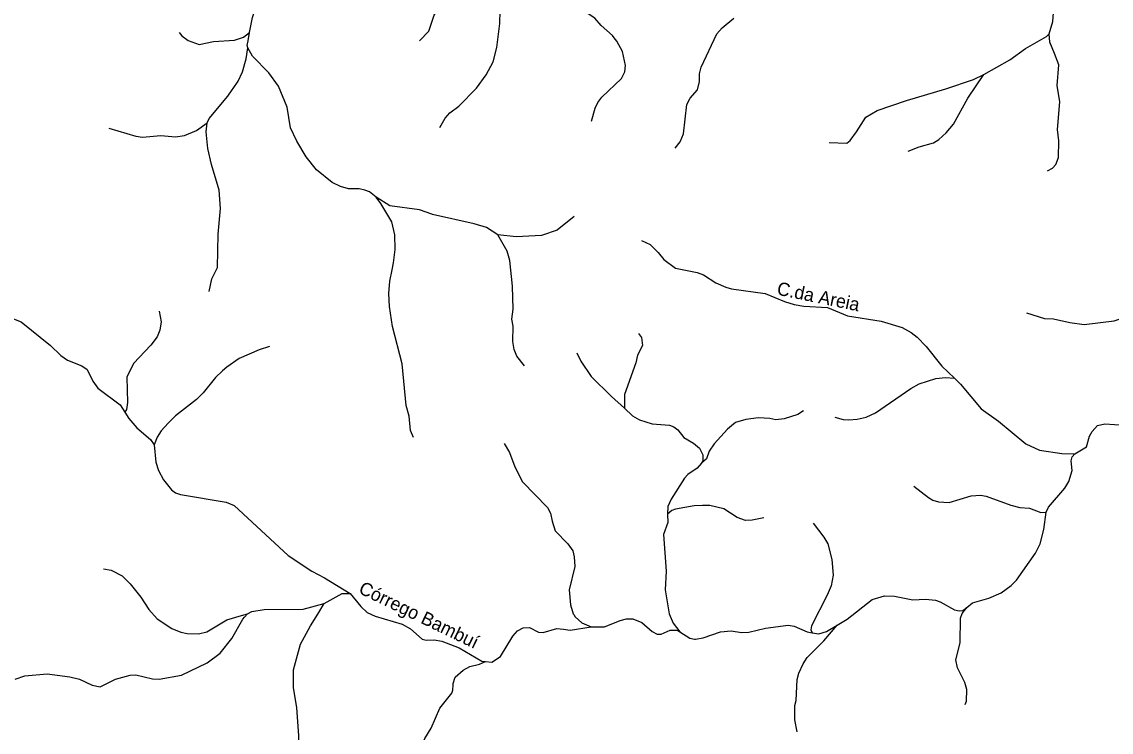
# Model space of a CAD drawing. Extents: x 473.9 to 500, y 7733.1 to 7760.8.
# Drawn here: x 487.72 to 494.3, y 7748.41 to 7752.7 of the extents above; entities that cross this region are included whole.
import ezdxf
from ezdxf.enums import TextEntityAlignment as Align

# ---------------------------------------------------------------- set-up
doc = ezdxf.new("R2010")
doc.units = 0
doc.header["$LTSCALE"] = 0.032
doc.layers.add('61', color=7, linetype='Continuous')
doc.layers.add('7', color=7, linetype='Continuous', lineweight=25)

msp = doc.modelspace()

# ---------------------------------------------------------------- linework, layer by layer
at = {"layer": '7'}
for points in [[(489.0978, 7752.6322), (489.1167, 7752.7232), (489.1826, 7752.9159), (489.2833, 7753.1268), (489.309, 7753.204), (489.3106, 7753.3927), (489.3298, 7753.4744), (489.3874, 7753.6027), (489.4117, 7753.6834), (489.4117, 7753.7508), (489.3957, 7753.837)], [(493.9278, 7752.6245), (493.9488, 7752.6981), (493.9547, 7752.7762), (493.9572, 7752.8085), (493.989, 7752.8897), (493.9899, 7752.984), (494, 7753.0158), (494.0416, 7753.0831), (494.0717, 7753.1527), (494.1019, 7753.199), (494.158, 7753.2503), (494.2408, 7753.2987)], [(490.1257, 7752.5825), (490.1808, 7752.6398), (490.2143, 7752.7373), (490.2748, 7752.8186), (490.3281, 7752.873), (490.4074, 7752.937), (490.4215, 7752.9588), (490.4461, 7753.0279), (490.4572, 7753.0844), (490.4612, 7753.1473)], [(490.2469, 7752.0579), (490.2808, 7752.1147), (490.3075, 7752.1466), (490.3632, 7752.1879), (490.4689, 7752.2953), (490.5273, 7752.3771), (490.5709, 7752.4549), (490.592, 7752.5405), (490.6095, 7752.6857), (490.6112, 7752.7625), (490.6078, 7752.8904), (490.5948, 7752.9581), (490.5682, 7753.0238), (490.5298, 7753.0816), (490.4612, 7753.1473)], [(491.1644, 7752.0963), (491.1858, 7752.1755), (491.2012, 7752.2098), (491.2269, 7752.2418), (491.3449, 7752.3536), (491.3649, 7752.3945), (491.368, 7752.4324), (491.3508, 7752.5182), (491.3173, 7752.5789), (491.3014, 7752.599), (491.29, 7752.6134), (491.222, 7752.6734), (491.1831, 7752.7195), (491.1264, 7752.757), (491.1058, 7752.7784), (491.084, 7752.8101), (491.0682, 7752.8725), (491.0895, 7752.934), (491.1537, 7753.0282), (491.1957, 7753.075), (491.2909, 7753.1607)], [(491.6683, 7751.9332), (491.6991, 7751.9725), (491.72, 7752.0205), (491.7402, 7752.1976), (491.7597, 7752.2349), (491.8034, 7752.2851), (491.8154, 7752.3364), (491.8155, 7752.382), (491.8249, 7752.4228), (491.9214, 7752.6246), (491.953, 7752.6609), (492.0237, 7752.718)], [(488.6739, 7752.6329), (488.6908, 7752.6119), (488.7275, 7752.5847), (488.7937, 7752.5602), (488.8816, 7752.5779), (489.0076, 7752.5854), (489.0631, 7752.6047), (489.0978, 7752.6322)], [(489.0885, 7752.5396), (489.0853, 7752.5526), (489.0898, 7752.5815), (489.0978, 7752.6322)], [(493.533, 7752.3781), (493.6895, 7752.4673), (493.7849, 7752.5363), (493.9107, 7752.6086), (493.9278, 7752.6245)], [(493.9169, 7751.7957), (493.9473, 7751.8136), (493.9673, 7751.8344), (493.9834, 7751.8762), (493.985, 7751.9779), (493.9779, 7752.0458), (493.9906, 7752.2137), (493.9747, 7752.3113), (493.985, 7752.4375), (493.9585, 7752.5056), (493.9321, 7752.5734), (493.9278, 7752.6245)], [(488.8427, 7752.0858), (488.8552, 7752.1123), (488.9685, 7752.2469), (488.9948, 7752.2864), (489, 7752.2942), (489.0294, 7752.3383), (489.0556, 7752.3939), (489.0782, 7752.4731), (489.0885, 7752.5396)], [(489.8633, 7751.6369), (489.8237, 7751.6692), (489.7941, 7751.6796), (489.7612, 7751.687), (489.6968, 7751.6879), (489.6477, 7751.7012), (489.5976, 7751.7263), (489.5038, 7751.8034), (489.4405, 7751.881), (489.3848, 7751.9765), (489.3461, 7752.0571), (489.3265, 7752.1817), (489.2747, 7752.3089), (489.215, 7752.3888), (489.1164, 7752.4898), (489.0885, 7752.5396)], [(492.5981, 7751.9672), (492.706, 7751.9629), (492.7252, 7751.9794), (492.7643, 7752.0312), (492.8193, 7752.1205), (492.8893, 7752.1612), (493.0666, 7752.2219), (493.3026, 7752.291), (493.471, 7752.3488), (493.533, 7752.3781)], [(493.0755, 7751.915), (493.1426, 7751.9426), (493.2294, 7751.9667), (493.2604, 7751.9852), (493.3049, 7752.0259), (493.3502, 7752.0778), (493.436, 7752.2365), (493.533, 7752.3781)], [(488.2502, 7752.0542), (488.4126, 7752.0054), (488.4517, 7752.0006), (488.563, 7752.0102), (488.651, 7752.0014), (488.7058, 7752.0109), (488.7781, 7752.0405), (488.8427, 7752.0858)], [(488.8554, 7751.0685), (488.8719, 7751.1444), (488.905, 7751.213), (488.9098, 7751.4151), (488.9227, 7751.5689), (488.9162, 7751.679), (488.8697, 7751.8342), (488.8473, 7751.9323), (488.8377, 7752.0327), (488.8427, 7752.0858)], [(490.0895, 7750.1852), (490.0708, 7750.2291), (490.0627, 7750.316), (490.0443, 7750.3804), (490.0201, 7750.631), (489.9611, 7750.8574), (489.9441, 7750.9779), (489.9409, 7751.0559), (489.9457, 7751.1297), (489.9598, 7751.1996), (489.9682, 7751.2416), (489.9778, 7751.3225), (489.9761, 7751.4102), (489.9576, 7751.4885), (489.8916, 7751.5999), (489.8633, 7751.6369)], [(490.5985, 7751.4106), (490.5305, 7751.4553), (490.455, 7751.4771), (490.2041, 7751.5329), (490.1994, 7751.5346), (490.1241, 7751.5614), (489.9463, 7751.5858), (489.8633, 7751.6369)], [(491.0581, 7751.5206), (490.9562, 7751.4386), (490.8613, 7751.4068), (490.709, 7751.3975), (490.5985, 7751.4106)], [(490.7592, 7750.6195), (490.712, 7750.6771), (490.6961, 7750.7171), (490.6882, 7750.7656), (490.6906, 7750.8578), (490.6834, 7750.9002), (490.6898, 7750.9618), (490.6873, 7751.1008), (490.6696, 7751.2556), (490.6535, 7751.3121), (490.5985, 7751.4106)], [(491.4659, 7751.3769), (491.5174, 7751.3516), (491.5666, 7751.3032), (491.6, 7751.2603), (491.6717, 7751.2097), (491.8017, 7751.1833), (491.8395, 7751.1682), (491.9154, 7751.1198), (491.9748, 7751.0941), (492.0098, 7751.0841), (492.2128, 7751.0561), (492.3292, 7751.0077), (492.3874, 7750.99), (492.4451, 7750.9797), (492.5886, 7750.971), (492.7104, 7750.9201), (492.9125, 7750.8892), (493.0389, 7750.85), (493.094, 7750.8213), (493.1309, 7750.7924), (493.1854, 7750.7348), (493.2795, 7750.6173), (493.355, 7750.5446)], [(487.5104, 7750.9522), (487.5248, 7750.9443), (487.5467, 7750.9322), (487.6635, 7750.9078), (487.7193, 7750.8848), (487.8966, 7750.7414), (487.9591, 7750.6809), (487.9995, 7750.6532), (488.0858, 7750.6197), (488.1184, 7750.5966), (488.1518, 7750.5266), (488.1819, 7750.4843), (488.3172, 7750.3825), (488.3468, 7750.3398)], [(488.5529, 7750.9487), (488.5658, 7750.884), (488.5571, 7750.8342), (488.541, 7750.7939), (488.503, 7750.7431), (488.3976, 7750.634), (488.3583, 7750.5509), (488.3613, 7750.3971), (488.3557, 7750.3545), (488.3468, 7750.3398)], [(493.7905, 7750.939), (493.8997, 7750.9054), (493.954, 7750.9029), (494.0511, 7750.8812), (494.138, 7750.8693), (494.3198, 7750.8913), (494.4091, 7750.9209), (494.4388, 7750.9308), (494.5097, 7750.9269), (494.635, 7750.8941), (494.6673, 7750.8998)], [(491.4469, 7750.814), (491.466, 7750.7899), (491.4706, 7750.7425), (491.4416, 7750.6842), (491.4319, 7750.6377), (491.3632, 7750.4455), (491.3622, 7750.3635)], [(489.2184, 7750.7352), (489.157, 7750.7153), (489.037, 7750.6642), (488.9618, 7750.6117), (488.9363, 7750.5883), (488.8939, 7750.5495), (488.8185, 7750.4563), (488.778, 7750.4152), (488.6511, 7750.3179), (488.6065, 7750.2733), (488.5655, 7750.2266), (488.5408, 7750.1874), (488.5232, 7750.1416)], [(491.0761, 7750.6982), (491.0999, 7750.6469), (491.1626, 7750.5547), (491.2836, 7750.4332), (491.3622, 7750.3635)], [(492.6325, 7750.3096), (492.6823, 7750.2958), (492.718, 7750.2927), (492.7668, 7750.2965), (492.8215, 7750.3093), (492.878, 7750.335), (493.0909, 7750.4813), (493.1431, 7750.5108), (493.2423, 7750.5428), (493.3014, 7750.5486), (493.355, 7750.5446)], [(493.355, 7750.5446), (493.3925, 7750.5085), (493.517, 7750.3599), (493.6216, 7750.2857), (493.7869, 7750.1472), (493.8678, 7750.1096), (494.0027, 7750.0893), (494.0813, 7750.088)], [(488.3468, 7750.3398), (488.3696, 7750.3012), (488.4185, 7750.2436), (488.5005, 7750.1751), (488.5232, 7750.1416)], [(491.3622, 7750.3635), (491.412, 7750.3164), (491.4534, 7750.2932), (491.5309, 7750.268), (491.6342, 7750.2598), (491.6599, 7750.251), (491.6841, 7750.2332), (491.7202, 7750.1853), (491.7795, 7750.1528), (491.8165, 7750.1217), (491.8361, 7750.0821), (491.8355, 7750.0466), (491.8273, 7750.0305)], [(492.4435, 7750.3478), (492.4101, 7750.3252), (492.3272, 7750.2984), (492.2773, 7750.2935), (492.24, 7750.3016), (492.1724, 7750.3047), (492.0961, 7750.2951), (492.0333, 7750.2766), (491.9852, 7750.2372), (491.905, 7750.1474), (491.8749, 7750.103), (491.8586, 7750.0571), (491.8273, 7750.0305)], [(494.0813, 7750.088), (494.1534, 7750.1295), (494.1716, 7750.1938), (494.1859, 7750.2224), (494.219, 7750.2588), (494.2637, 7750.2686), (494.38, 7750.2599), (494.4179, 7750.2662)], [(488.5232, 7750.1416), (488.5323, 7750.0378), (488.5495, 7749.9879), (488.5798, 7749.9302), (488.6279, 7749.8705), (488.6526, 7749.8522), (488.6826, 7749.8415), (488.9569, 7749.7947), (489.007, 7749.7759), (489.332, 7749.4742), (489.4747, 7749.3794), (489.5522, 7749.339), (489.7059, 7749.245)], [(490.6355, 7750.1505), (490.6687, 7750.0966), (490.7011, 7750.0095), (490.7468, 7749.9181), (490.8984, 7749.7633), (490.9167, 7749.7287), (490.9255, 7749.6806), (490.9449, 7749.6227), (491.021, 7749.5444), (491.0504, 7749.5021), (491.0594, 7749.4654), (491.0625, 7749.408), (491.0297, 7749.2659), (491.0361, 7749.1761), (491.0539, 7749.1211), (491.0571, 7749.1165), (491.0655, 7749.104), (491.1056, 7749.0678), (491.1612, 7749.043)], [(493.9084, 7749.7359), (493.9227, 7749.765), (494.0223, 7749.8809), (494.0467, 7749.9196), (494.0652, 7749.9876), (494.0596, 7750.0445), (494.0657, 7750.0687), (494.0813, 7750.088)], [(491.8273, 7750.0305), (491.8007, 7750.0013), (491.7454, 7749.9629), (491.7251, 7749.941), (491.6443, 7749.8134), (491.6249, 7749.7698), (491.6235, 7749.7229)], [(493.1107, 7749.8921), (493.1983, 7749.8233), (493.2241, 7749.8075), (493.2586, 7749.7985), (493.3233, 7749.7941), (493.4555, 7749.8349), (493.5133, 7749.8382), (493.5462, 7749.8323), (493.6955, 7749.7773), (493.7506, 7749.7636), (493.8093, 7749.7586), (493.8776, 7749.7336), (493.9084, 7749.7359)], [(492.2033, 7749.7008), (492.1332, 7749.6866), (492.0941, 7749.6858), (492.0426, 7749.7036), (491.9624, 7749.7562), (491.8774, 7749.7756), (491.8329, 7749.7748), (491.7836, 7749.774), (491.6714, 7749.7532), (491.6485, 7749.7457), (491.6235, 7749.7229)], [(493.4302, 7749.1605), (493.4647, 7749.188), (493.5625, 7749.2154), (493.6377, 7749.2485), (493.6978, 7749.2927), (493.7306, 7749.3256), (493.8449, 7749.4872), (493.8728, 7749.5446), (493.8952, 7749.6309), (493.9084, 7749.7359)], [(491.6235, 7749.7229), (491.6246, 7749.6733), (491.5974, 7749.6008), (491.6141, 7749.3795), (491.6086, 7749.2665), (491.6335, 7749.121), (491.6576, 7749.0657), (491.6963, 7749.0127)], [(492.5023, 7749.6697), (492.5669, 7749.5845), (492.5903, 7749.5436), (492.6156, 7749.4487), (492.6237, 7749.3546), (492.6112, 7749.2908), (492.5874, 7749.2332), (492.4917, 7749.0486), (492.4882, 7749.0251), (492.4954, 7749.0059)], [(488.2179, 7749.3934), (488.2639, 7749.384), (488.3301, 7749.35), (488.3788, 7749.3028), (488.4425, 7749.2221), (488.491, 7749.1468), (488.5407, 7749.091), (488.6305, 7749.032), (488.6834, 7749.0103), (488.7215, 7749.0027), (488.7913, 7749.0011), (488.8417, 7749.0116), (488.9619, 7749.0844), (489.05, 7749.1107), (489.0857, 7749.1213)], [(489.5501, 7749.1833), (489.6585, 7749.2431), (489.7059, 7749.245)], [(489.7059, 7749.245), (489.7705, 7749.1662), (489.8092, 7749.1297), (489.8578, 7749.1068), (490.0197, 7749.0595), (490.0701, 7749.0304), (490.1416, 7748.9689), (490.1657, 7748.9619), (490.2141, 7748.9641), (490.2596, 7748.9557), (490.3652, 7748.9163), (490.5007, 7748.8352), (490.524, 7748.8333)], [(492.6472, 7749.0532), (492.7073, 7749.0894), (492.8582, 7749.2071), (492.9331, 7749.2295), (492.9932, 7749.2286), (493.1044, 7749.2056), (493.1813, 7749.2103), (493.241, 7749.2039), (493.2698, 7749.1943), (493.3557, 7749.1448), (493.3846, 7749.139), (493.4055, 7749.1417), (493.4302, 7749.1605)], [(488.9484, 7747.9844), (488.9713, 7748.0211), (489.0022, 7748.0511), (489.0516, 7748.0781), (489.1553, 7748.1088), (489.1871, 7748.1399), (489.2107, 7748.1811), (489.2464, 7748.2122), (489.2732, 7748.2263), (489.3574, 7748.2526), (489.3939, 7748.2965), (489.3956, 7748.3857), (489.3844, 7748.554), (489.3636, 7748.6764), (489.3644, 7748.7832), (489.407, 7748.9372), (489.4664, 7749.0481), (489.5109, 7749.12), (489.5501, 7749.1833)], [(489.0857, 7749.1213), (489.1119, 7749.1349), (489.1881, 7749.1469), (489.4226, 7749.1499), (489.5501, 7749.1833)], [(493.4197, 7748.5744), (493.4281, 7748.5939), (493.43, 7748.6639), (493.4173, 7748.7063), (493.3733, 7748.7949), (493.3644, 7748.8429), (493.3902, 7748.9469), (493.3914, 7749.0955), (493.4015, 7749.1232), (493.4302, 7749.1605)], [(487.6827, 7748.7274), (487.7421, 7748.7477), (487.8771, 7748.7589), (488.0137, 7748.7412), (488.0718, 7748.7266), (488.1481, 7748.6899), (488.1962, 7748.6804), (488.2902, 7748.7262), (488.3781, 7748.7502), (488.4114, 7748.7525), (488.5133, 7748.7282), (488.553, 7748.7268), (488.6885, 7748.7505), (488.8436, 7748.8249), (488.9213, 7748.8844), (488.9911, 7748.9732), (489.0579, 7749.0884), (489.068, 7749.1004), (489.0857, 7749.1213)], [(491.1612, 7749.043), (491.2426, 7749.042), (491.3368, 7749.0812), (491.3741, 7749.0908), (491.4132, 7749.0916), (491.4668, 7749.0696), (491.53, 7749.0148), (491.5601, 7748.998), (491.5834, 7748.9986), (491.6391, 7749.0235), (491.6788, 7749.0219), (491.6963, 7749.0127)], [(490.524, 7748.8333), (490.5614, 7748.8303), (490.6148, 7748.8628), (490.6886, 7748.9872), (490.7175, 7749.0183), (490.7513, 7749.0372), (490.7891, 7749.0379), (490.8446, 7749.0109), (490.8714, 7749.0094), (490.9543, 7749.0331), (490.9955, 7749.0283), (491.0357, 7749.0236), (491.1612, 7749.043)], [(491.6963, 7749.0127), (491.7578, 7748.9739), (491.7853, 7748.9674), (491.7916, 7748.9685), (491.8385, 7748.977), (491.9418, 7749.0122), (492.0074, 7749.0179), (492.069, 7749.0086), (492.114, 7749.0108), (492.2147, 7749.0347), (492.3514, 7749.0523), (492.3879, 7749.0475), (492.466, 7749.0119), (492.4954, 7749.0059)], [(492.4046, 7748.4086), (492.3912, 7748.4806), (492.3912, 7748.5674), (492.3991, 7748.5972), (492.4056, 7748.7252), (492.416, 7748.7621), (492.4417, 7748.8198), (492.4666, 7748.8569), (492.5672, 7748.9591), (492.6472, 7749.0532)], [(492.4954, 7749.0059), (492.5354, 7749.0003), (492.5822, 7749.0141), (492.6472, 7749.0532)], [(489.8103, 7747.494), (489.8078, 7747.506), (489.818, 7747.562), (489.873, 7747.6434), (489.8883, 7747.716), (489.9461, 7747.8383), (489.9513, 7747.9247), (489.9823, 7748.0223), (490.0887, 7748.2095), (490.1271, 7748.2896), (490.1564, 7748.369), (490.1952, 7748.4305), (490.2476, 7748.5514), (490.3203, 7748.6421), (490.3273, 7748.6595), (490.328, 7748.6918), (490.3282, 7748.6999), (490.341, 7748.738), (490.3882, 7748.7805), (490.4292, 7748.8038), (490.4871, 7748.817), (490.524, 7748.8333)]]:
    msp.add_lwpolyline(points, dxfattribs=at)

# ---------------------------------------------------------------- texts
at = {"layer": '61'}
for s, rotation, p in [('C.da Areia', 348.369, (492.5261, 7750.9989)), ('Córrego Bambuí', 334.202, (490.105, 7749.0786))]:
    msp.add_text(s, height=0.08, rotation=rotation, dxfattribs=at).set_placement(p, align=Align.CENTER)

doc.saveas('drawing.dxf')
